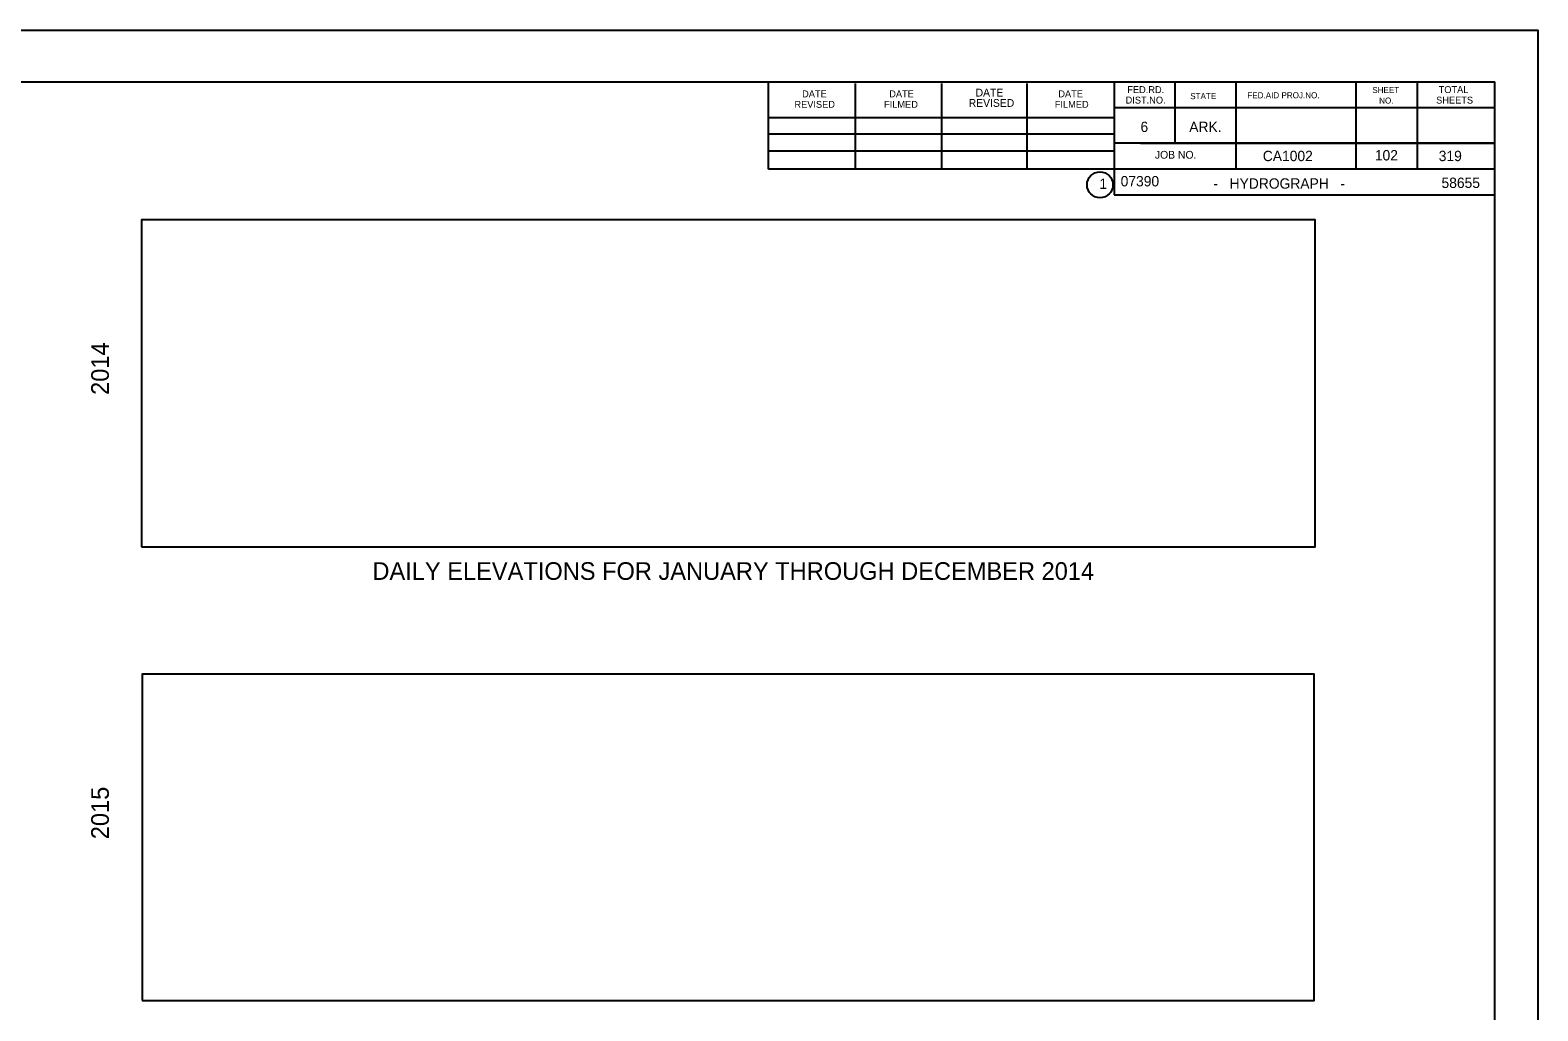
# Model space of a CAD drawing. Extents: x -1063117.8 to -1063083.7, y -253323.4 to -253301.6.
# Drawn here: x -1063100.74 to -1063083.66, y -253312.74 to -253301.63 of the extents above; entities that cross this region are included whole.
import ezdxf

# ---------------------------------------------------------------- set-up
doc = ezdxf.new("R2010")
doc.units = 0
for name, color, linetype in [('B_No_Plot', 7, 'Continuous'), ('border', 7, 'Continuous'), ('Bridge No Ditch 81', 7, 'Continuous'), ('Dimensions', 7, 'Continuous'), ('Level 62', 7, 'Continuous'), ('Text', 7, 'Continuous'), ('Title Text', 7, 'Continuous')]:
    doc.layers.add(name, color=color, linetype=linetype)

msp = doc.modelspace()

# ---------------------------------------------------------------- linework, layer by layer
at = {"layer": 'B_No_Plot'}
msp.add_lwpolyline([(-1063099.465, -253312.623), (-1063086.191, -253312.623), (-1063086.191, -253308.924), (-1063099.465, -253308.924)], close=True, dxfattribs=at)
at = {"layer": 'border'}
for p, q in [((-1063116.157, -253302.216), (-1063084.146, -253302.216)), ((-1063092.372, -253303.204), (-1063092.372, -253302.216)), ((-1063091.387, -253303.204), (-1063091.387, -253302.235)), ((-1063090.41, -253303.204), (-1063090.41, -253302.235)), ((-1063089.443, -253303.204), (-1063089.443, -253302.235)), ((-1063088.456, -253302.216), (-1063088.456, -253303.495)), ((-1063087.772, -253302.216), (-1063087.772, -253302.91)), ((-1063087.078, -253302.216), (-1063087.078, -253303.204)), ((-1063085.72, -253302.216), (-1063085.72, -253303.204)), ((-1063085.026, -253302.216), (-1063085.026, -253303.204)), ((-1063084.146, -253322.761), (-1063084.146, -253302.216)), ((-1063092.372, -253302.618), (-1063088.456, -253302.618)), ((-1063084.146, -253302.51), (-1063088.456, -253302.51)), ((-1063084.146, -253302.508), (-1063084.146, -253302.508)), ((-1063092.372, -253302.804), (-1063088.456, -253302.804)), ((-1063084.146, -253302.91), (-1063088.456, -253302.91)), ((-1063088.16, -253302.91), (-1063084.146, -253302.91)), ((-1063092.372, -253303.204), (-1063092.372, -253302.997)), ((-1063092.372, -253302.997), (-1063088.456, -253302.997)), ((-1063084.146, -253303.204), (-1063092.372, -253303.204)), ((-1063088.456, -253303.495), (-1063084.146, -253303.495))]:
    msp.add_line(p, q, dxfattribs=at)
msp.add_circle((-1063088.618, -253303.382), 0.147, dxfattribs=at)
at = {"layer": 'Dimensions'}
msp.add_lwpolyline([(-1063099.473, -253307.483), (-1063086.182, -253307.483), (-1063086.182, -253303.779), (-1063099.473, -253303.779)], close=True, dxfattribs=at)
at = {"layer": 'Level 62'}
msp.add_lwpolyline([(-1063117.777, -253301.63), (-1063083.659, -253301.63), (-1063083.659, -253323.44), (-1063117.777, -253323.44)], close=True, dxfattribs=at)

# ---------------------------------------------------------------- texts
at = {"layer": 'Bridge No Ditch 81'}
msp.add_text('07390', height=0.1172, dxfattribs=at).set_placement((-1063088.384, -253303.4))
at = {"layer": 'Text'}
for s, height, p in [('FED.RD.', 0.0782, (-1063088.309, -253302.343)), ('SHEET', 0.0684, (-1063085.534, -253302.343)), ('TOTAL', 0.0782, (-1063084.782, -253302.343)), ('REVISED', 0.0782, (-1063092.079, -253302.51)), ('DATE', 0.0782, (-1063091.992, -253302.391)), ('FILMED', 0.0782, (-1063091.064, -253302.51)), ('DATE', 0.0782, (-1063091.005, -253302.391)), ('REVISED', 0.0879, (-1063090.105, -253302.499)), ('DATE', 0.0879, (-1063090.027, -253302.382)), ('FILMED', 0.0782, (-1063089.13, -253302.51)), ('DATE', 0.0782, (-1063089.09, -253302.391)), ('DIST.NO.', 0.0782, (-1063088.328, -253302.462)), ('STATE', 0.0684, (-1063087.596, -253302.412)), ('FED.AID PROJ.NO.', 0.06839, (-1063086.949, -253302.402)), ('NO.', 0.0684, (-1063085.456, -253302.462)), ('SHEETS', 0.0782, (-1063084.811, -253302.462)), ('6', 0.117, (-1063088.159, -253302.784)), ('ARK.', 0.1172, (-1063087.607, -253302.784)), ('JOB NO.', 0.0879, (-1063087.996, -253303.086)), ('CA1002', 0.1172, (-1063086.774, -253303.114)), ('102', 0.1172, (-1063085.505, -253303.106)), ('319', 0.1172, (-1063084.781, -253303.114)), ('1', 0.117, (-1063088.625, -253303.429))]:
    msp.add_text(s, height=height, dxfattribs=at).set_placement(p)
at = {"layer": 'Title Text'}
for s, height, p in [('58655', 0.1172, (-1063084.75, -253303.418)), ('-   HYDROGRAPH   -', 0.11722, (-1063087.333, -253303.426)), (' DAILY ELEVATIONS FOR JANUARY THROUGH DECEMBER 2014 ', 0.2, (-1063096.933, -253307.857))]:
    msp.add_text(s, height=height, dxfattribs=at).set_placement(p)
for s, p in [('2014', (-1063099.844, -253305.762)), ('2015', (-1063099.844, -253310.795))]:
    msp.add_text(s, height=0.2, rotation=90, dxfattribs=at).set_placement(p)

doc.saveas('drawing.dxf')
